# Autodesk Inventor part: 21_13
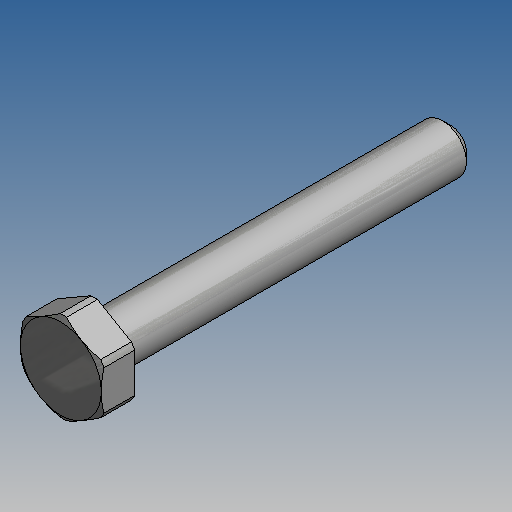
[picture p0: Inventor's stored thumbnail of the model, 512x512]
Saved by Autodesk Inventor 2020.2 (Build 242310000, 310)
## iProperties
Part Number: 21_13
Material: Generic
Document SubType Name: Modeling
Designer: amoles
Appearance: Default
Author: amoles
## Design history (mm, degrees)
feature "Base1"
body "Solid1"
